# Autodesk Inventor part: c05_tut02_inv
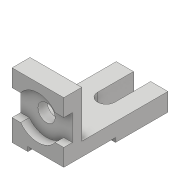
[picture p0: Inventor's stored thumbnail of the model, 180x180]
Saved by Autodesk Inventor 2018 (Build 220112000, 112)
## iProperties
Created: 2017-04
Part Number: c05_tut02_inv
Material: Generic
Document SubType Name: Modeling
Designer: CADCIM 00
Density: 1 g/cm^3
Appearance: Default
Author: CADCIM 00
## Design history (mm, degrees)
sketch "Sketch1"
  geometry: L1 (0, 0)-(0, 90); L2 (0, 90)-(25, 90); L3 (25, 90)-(25, 25); L4 (25, 25)-(145, 25); L5 (145, 25)-(145, 0); L6 (145, 0)-(0, 0)
  constraints: 12 end point, 6 perpendicular, 1 vertical
  dimensions: "d0" = 90 distance of L1.start L1.end; "d1" = 25 distance of L1.end L2.end; "d2" = 145 distance of L5.end L1.start
extrude "Extrusion1" new body sketch "Sketch1" stored distance "d3" = 72; taper "d4" = 0 deg
sketch "Sketch2"
  geometry: L1 (0, 0)-(0, 145) reference; L2 (0, 0)-(-6, 0); L3 (-6, 0)-(-6, 72); L4 (-6, 72)-(0, 72); L5 (0, 72)-(0, 0)
  constraints: 8 end point, 2 parallel, 1 horizontal, 1 perpendicular
  dimensions: "d5" = 72 distance between parallel lines of L4 L2; "d6" = 6 distance between parallel lines of L1 L3
extrude "Extrusion2" cut sketch "Sketch2" distance "d7" = 50; taper "d8" = 0 deg
sketch "Sketch3"
  geometry: L1 (0, 0)-(0, -65) reference; L2 (72, -65)-(72, 0) reference; L3 (72, -24)-(72, -60); L4 (0, -60)-(0, -24); L5 (0, -24)-(12, -24); L6 (60, -24)-(72, -24); L7 (72, -60)-(60, -60); L8 (12, -60)-(0, -60); L9 (72, -90)-(22, -90) reference; L10 (0, -90)-(22, -90) reference; A1 r 30 centre (36, -42) between (12, -60) and (60, -60); A2 r 30 centre (36, -42) between (60, -24) and (12, -24); 1 further point
  constraints: 12 end point, 5 parallel, 4 point on circle, 2 centre point, 2 collinear, 2 horizontal, 2 perpendicular, 2 point on line, 1 concentric
  dimensions: "d9" = 30 radius of A2; "d10" = 48 distance from line of L9 A1.centre; "d11" = 36 distance from line of L1 A1.centre; "d12" = 36 distance between parallel lines of L8 L5; "d13" = 30 distance between parallel lines of L10 L8
extrude "Extrusion3" cut sketch "Sketch3" distance "d14" = 12; taper "d15" = 0 deg
sketch "Sketch4"
  geometry: C1 r 12 at (36, -42); A1 r 30 centre (36, -42) between (60, -24) and (12, -24) reference; 1 further point
  constraints: 1 centre point, 1 concentric
  dimensions: "d16" = 24 diameter of C1
extrude "Extrusion4" cut sketch "Sketch4" stored distance "d17" = 12; taper "d18" = 0 deg
sketch "Sketch5"
  geometry: L1 (36, 119.693)-(36, 70); L2 (24, 119.693)-(24, 70); L3 (48, 70)-(48, 120); L4 (72, 120)-(0, 120) reference; L5 (24.004, 120)-(48, 120); L6 (72, 120)-(0, 120) reference; L7 (72, 120)-(72, 0) reference; A1 r 12 centre (36, 70) between (24, 70) and (48, 70); A2 r 12 centre (36, 119.693) between (24.004, 120) and (24, 119.693); 2 further points
  constraints: 10 end point, 4 point on circle, 3 tangent, 2 centre point, 2 point on line, 2 vertical, 1 collinear, 1 midpoint, 1 parallel
  dimensions: "d19" = 50 distance from line of L1.end L4; "d20" = 12 radius of A1; "d21" = 36 distance between parallel lines of L7 L1
extrude "Extrusion5" cut sketch "Sketch5" extent not by distance; stored distance "d22" = 12; taper "d23" = 0 deg
body "Solid1"
